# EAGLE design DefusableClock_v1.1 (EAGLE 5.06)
REV: 1.0
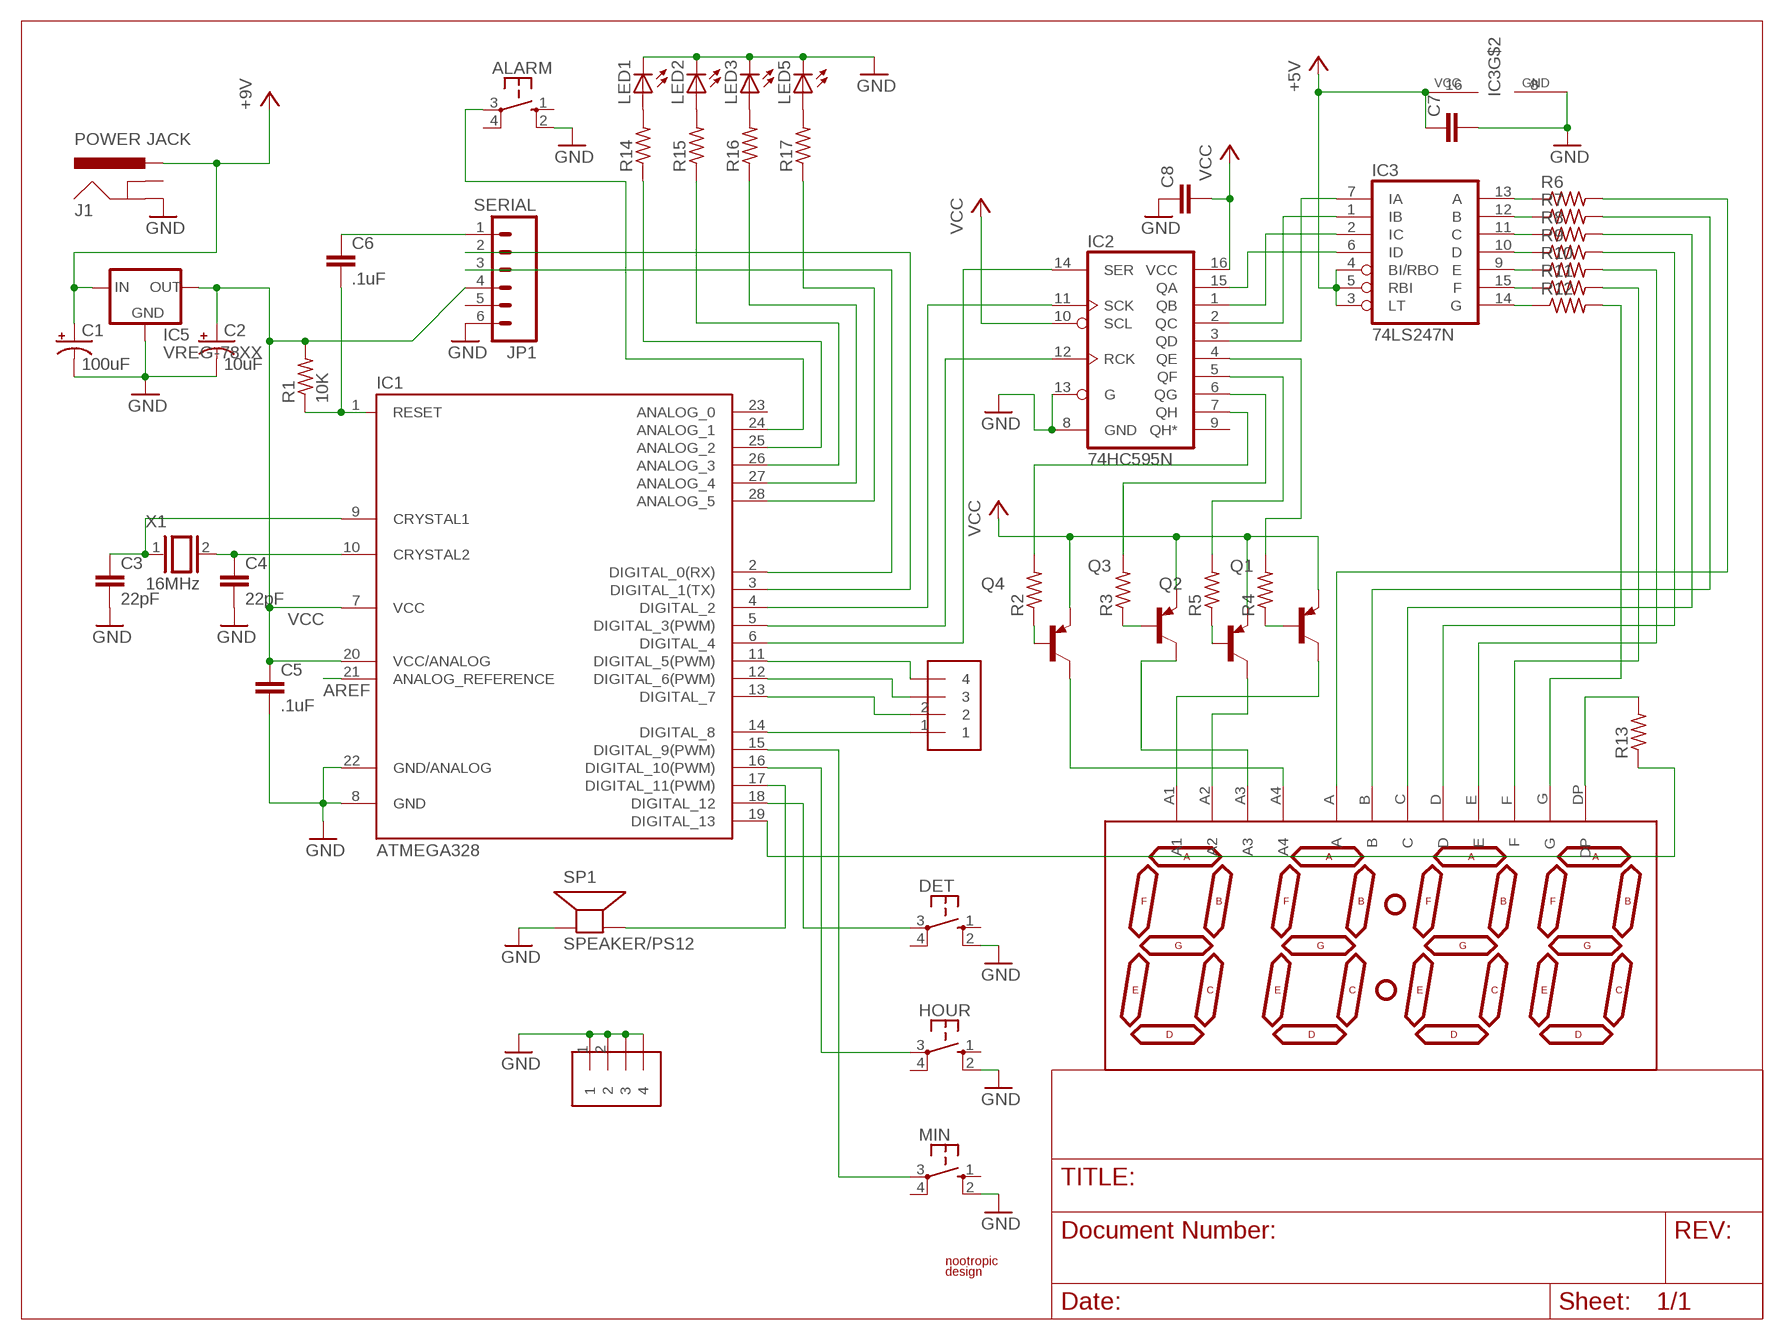
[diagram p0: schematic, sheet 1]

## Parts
ALARM  SWITCH-TACT  [SWITCH-TACT]
C1  100uF  CAP-POL6MM  [E2.5-6]
C2  10uF  CAP-POL5MM  [E2.5-5]
C3  22pF  CAP  [CAP-CERAMIC]
C4  22pF  CAP  [CAP-CERAMIC]
C5  .1uF  CAPSMALL  [CAP-CERAMIC-SMALL]
C6  .1uF  CAPSMALL  [CAP-CERAMIC-SMALL]
C7  CAPSMALL  [CAP-CERAMIC-SMALL]
C8  CAPSMALL  [CAP-CERAMIC-SMALL]
C9  1X4-TERMINAL-BLOCK  [1X4-TERMINAL]
C10  1X4-TERMINAL-BLOCK  [1X4-TERMINAL]
D1  7-SEGMENT-DISPLAY-4DIGIT  [7-SEGMENT-DISPLAY-4DIGIT]
DET  SWITCH-TACT12MM  [SWITCH-12MM]
HOUR  SWITCH-TACT  [SWITCH-TACT]
IC1  ATMEGA328  ATMEGA168-PU  [DIL28-3]
IC2  74HC595N  74LS595N  [DIL16]
IC3  74LS247N  74LS47N  [DIL16]
IC5  VREG-78XX  [78XXL]
J1  POWER JACK  POWER_JACKPTH  [POWER_JACK_PTH]
JP1  SERIAL  M06  [1X06]
LED1  LED3MM  [LED3MM]
LED2  LED3MM  [LED3MM]
LED3  LED3MM  [LED3MM]
LED5  LED3MM  [LED3MM]
MIN  SWITCH-TACT  [SWITCH-TACT]
Q1  -PNP-TO92-EBC  [TO92-EBC]
Q2  -PNP-TO92-EBC  [TO92-EBC]
Q3  -PNP-TO92-EBC  [TO92-EBC]
Q4  -PNP-TO92-EBC  [TO92-EBC]
R1  10K  R-US  [0207/10]
R2  R-US  [0207/10]
R3  R-US  [0207/10]
R4  R-US  [0207/10]
R5  R-US  [0207/10]
R6  R-US  [0207/10]
R7  R-US  [0207/10]
R8  R-US  [0207/10]
R9  R-US  [0207/10]
R10  R-US  [0207/10]
R11  R-US  [0207/10]
R12  R-US  [0207/10]
R13  R-US  [0207/10]
R14  R-US  [0207/10]
R15  R-US  [0207/10]
R16  R-US  [0207/10]
R17  R-US  [0207/10]
SP1  SPEAKER/PS12  [PS12]
U$1  LOGO  [LOGO_SMALL]
X1  16MHz  XTAL/S  [QS]

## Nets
A: D1.A R6.2
A1: D1.A1 Q1.C
A2: D1.A2 Q2.C
A3: D1.A3 Q3.C
A4: D1.A4 Q4.C
ALARM: ALARM.3(P) IC1.24(ANALOG_1)
AREF: IC1.21(ANALOG_REFERENCE)
ASINK: IC3.13(A) R6.1
B: D1.B R7.2
BSINK: IC3.12(B) R7.1
C: D1.C R8.2
CLOCK: IC1.4(DIGITAL_2) IC2.11(SCK)
CSINK: IC3.11(C) R8.1
D: D1.D R9.2
DATA: IC1.6(DIGITAL_4) IC2.14(SER)
DP: D1.DP R13.2
DSINK: IC3.10(D) R9.1
E: D1.E R10.2
ESINK: IC3.9(E) R10.1
F: D1.F R11.2
FSINK: IC3.15(F) R11.1
G: D1.G R12.2
GND: ALARM.2(S1) C1.- C2.- C3.2 C4.2 C5.2 C7.2 C8.1 C9.1 C9.2 C9.3 C9.4 DET.2(S1) HOUR.2(S1) IC1.8(GND) IC1.22(GND/ANALOG) IC2.8(GND) IC2.13(G) IC3.8(GND) IC5.GND J1.GND JP1.6 LED1.K(C) LED2.K(C) LED3.K(C) LED5.K(C) MIN.2(S1) SP1.P$1(+)
GSINK: IC3.14(G) R12.1
LATCH: IC1.5(DIGITAL_3(PWM)) IC2.12(RCK)
N$1: IC1.17(DIGITAL_11(PWM)) SP1.P$2(-)
N$2: IC2.3(QD) IC3.7(IA)
N$3: Q3.B R3.1
N$4: C4.1 IC1.10(CRYSTAL2) X1.2
N$5: Q2.B R5.1
N$6: C3.1 IC1.9(CRYSTAL1) X1.1
N$7: C6.2 IC1.1(RESET) R1.1
N$8: Q4.B R2.1
N$9: C6.1 JP1.1
N$10: IC2.2(QC) IC3.1(IB)
N$11: IC2.1(QB) IC3.2(IC)
N$12: IC2.15(QA) IC3.6(ID)
N$13: IC1.19(DIGITAL_13) R13.1
N$18: Q1.B R4.1
N$19: IC2.7(QH) R2.2
N$20: IC2.6(QG) R3.2
N$21: IC2.5(QF) R5.2
N$22: IC2.4(QE) R4.2
N$23: DET.3(P) IC1.18(DIGITAL_12)
N$24: HOUR.3(P) IC1.16(DIGITAL_10(PWM))
N$25: IC1.15(DIGITAL_9(PWM)) MIN.3(P)
N$26: LED1.A R14.2
N$27: LED2.A R15.2
N$28: LED3.A R16.2
N$29: IC1.28(ANALOG_5) R17.1
N$30: LED5.A R17.2
N$31: IC1.25(ANALOG_2) R14.1
N$32: IC1.26(ANALOG_3) R15.1
N$33: IC1.27(ANALOG_4) R16.1
RX: IC1.2(DIGITAL_0(RX)) JP1.3
TX: IC1.3(DIGITAL_1(TX)) JP1.2
VCC: C2.+ C5.1 C7.1 C8.2 IC1.7(VCC) IC1.20(VCC/ANALOG) IC2.10(SCL) IC2.16(VCC) IC3.3(LT) IC3.4(BI/RBO) IC3.5(RBI) IC3.16(VCC) IC5.OUT JP1.4 Q1.E Q2.E Q3.E Q4.E R1.2 ; supply symbol labelled +5V
VIN: C1.+ IC5.IN J1.PWR ; supply symbol labelled +9V
WIRE1: C10.4 IC1.11(DIGITAL_5(PWM))
WIRE2: C10.3 IC1.12(DIGITAL_6(PWM))
WIRE3: C10.2 IC1.13(DIGITAL_7)
WIRE4: C10.1 IC1.14(DIGITAL_8)
Unconnected: ALARM.1(S) ALARM.4(P1) DET.1(S) DET.4(P1) HOUR.1(S) HOUR.4(P1) IC1.23(ANALOG_0) IC2.9(QH*) J1.GNDBREAK JP1.5 MIN.1(S) MIN.4(P1)

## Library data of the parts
ALARM DET HOUR MIN = nootropicdesign:SWITCH-TACT: 12MM Tactile Switch
C1 C2 = nootropicdesign:CAP-POL: Capacitor - Polarized, Electrolytic
C3-C8 = nootropicdesign:CAP: Unpolarized capacitor
C9 C10 = nootropicdesign:1X4-TERMINAL-BLOCK
D1 = nootropicdesign:7-SEGMENT-DISPLAY-4DIGIT
IC1 = Arduino-AVR:ATMEGA168-PU
IC2 = nootropicdesign:74*595: 8-bit SHIFT REGISTER, output latch
IC3 = 74xx-us:74*47: BCD to seven segment DECODER/DRIVER Source: http://www.ee.washington.edu/stores/DataSheets/74ls/74ls47.pdf
IC5 = nootropicdesign:VREG-78XX
J1 = SparkFun:POWER_JACK: Power Jack This is the standard 5.5mm barrel jack for power. The PTH is the most common, proven, reliable, footprint. All others are experimental. The Slot footprint only works if the mill layer is transmitted to the PCB fab house so be warned. Spark Fun Electronics SKU : PRT-00119. Mating wall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
JP1 = nootropicdesign:M06: 6-pin header
LED1-LED3 LED5 = adafruit:LED: LED
Q1-Q4 = transistor-neu-to92:*-PNP-: PNP Transistror
R1-R17 = nootropicdesign:R-US: Resistor
SP1 = adafruit:SPEAKER: SPEAKER
U$1 = nootropicdesign:LOGO
X1 = special:XTAL/S: CRYSTAL

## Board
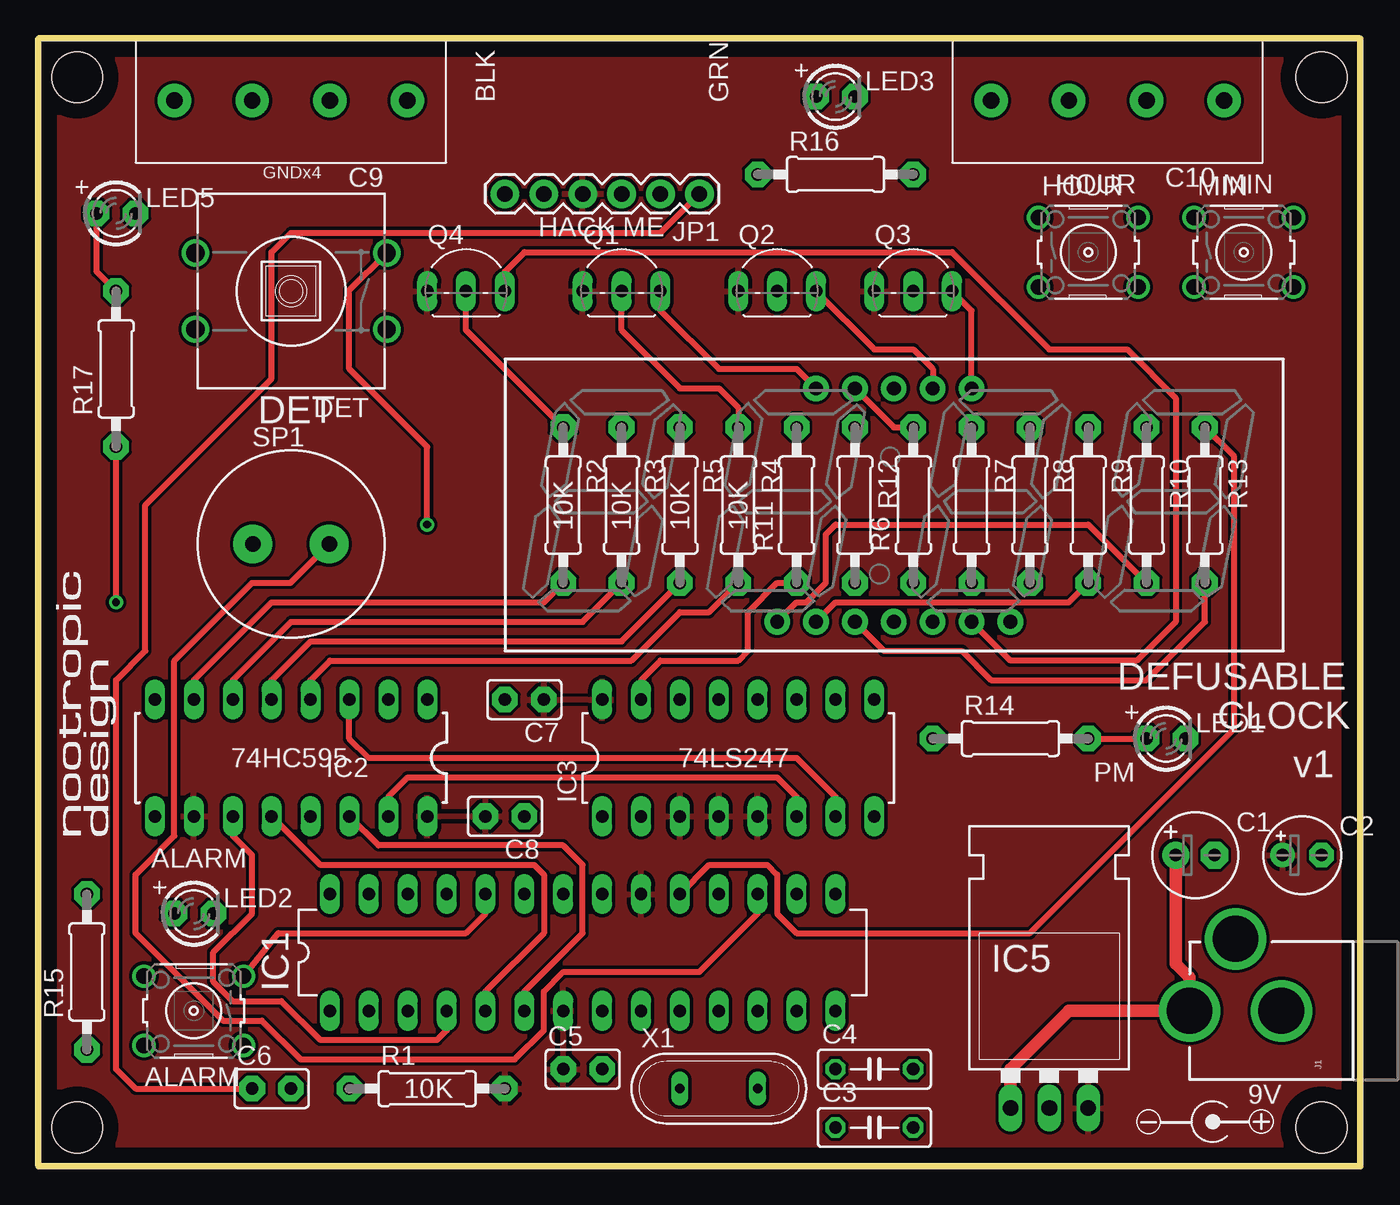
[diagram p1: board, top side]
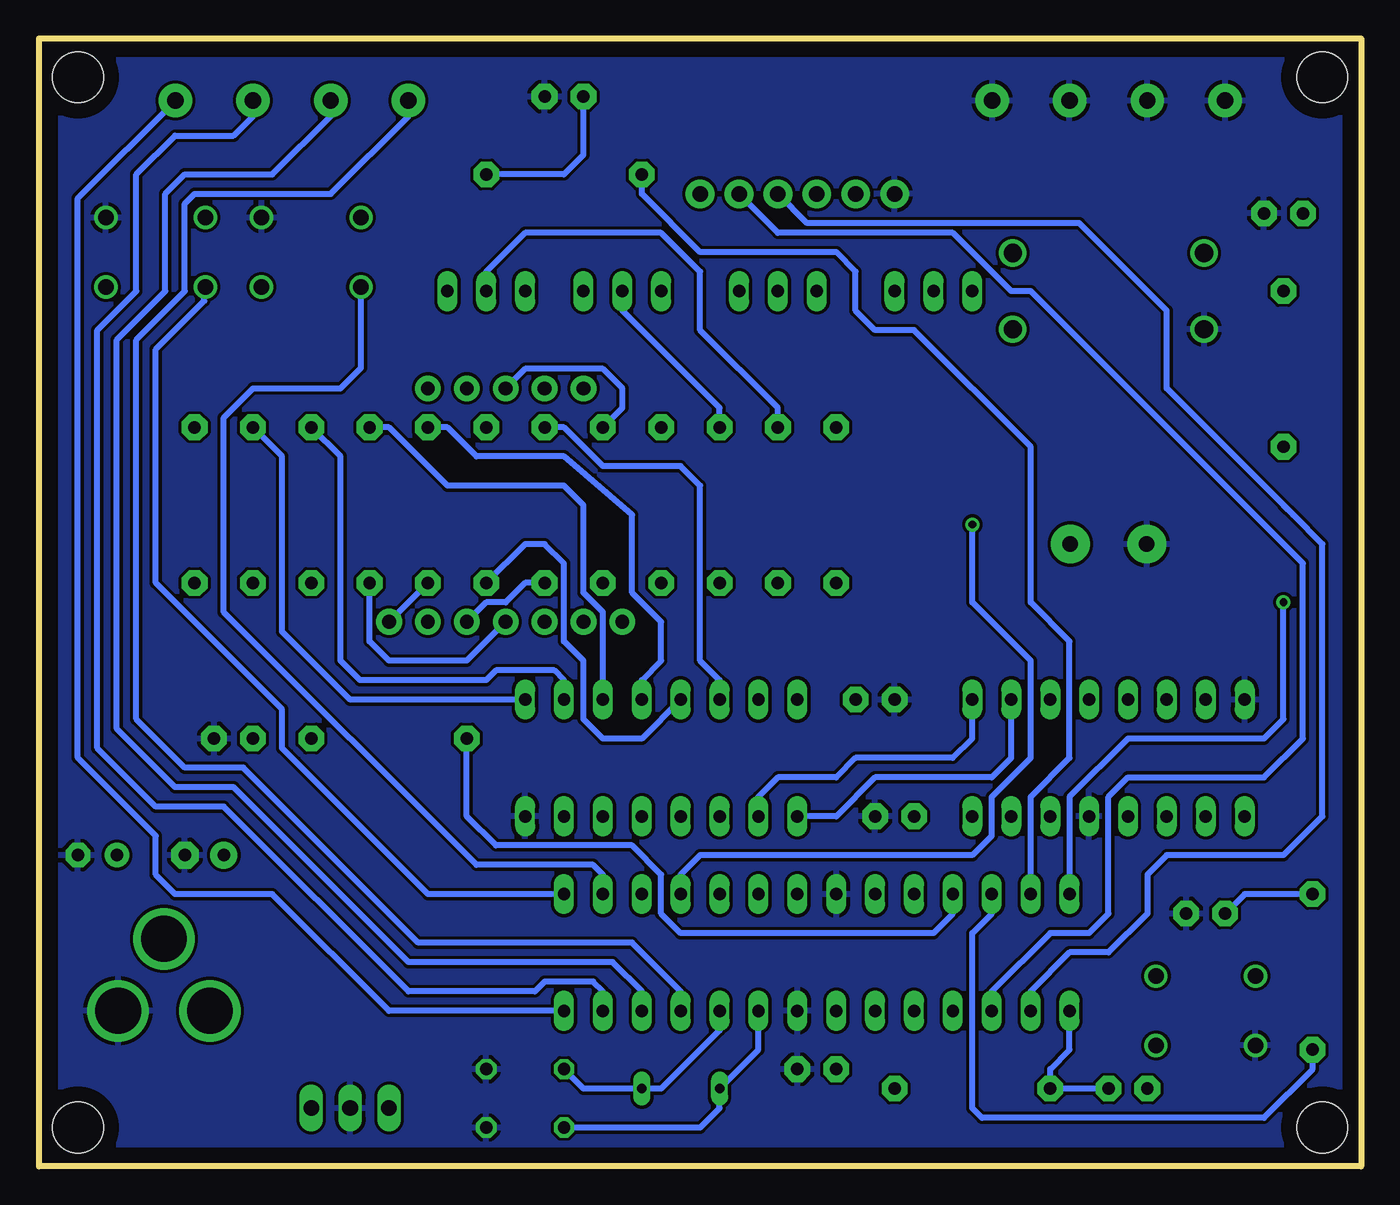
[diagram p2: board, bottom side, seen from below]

Size 86.41 x 73.66 mm. Coordinates in mm from the lower left corner, seen from the top.
Outline: 86.36,0 86.41,0 86.41,73.65 0,73.65 0,0
Outline: 0,0 86.36,0
Outline: 86.36,0 86.36,73.66 0,73.66 0,0
Copper layers (1*16): Top 0.035mm / dielectric 1.5mm / Bottom 0.035mm
Design rules "default *": minimum track width 10mil, minimum drill 20mil, track to track 8mil, track to pad 8mil, pad to pad 8mil, via to via 8mil, smd to smd 8mil, copper to edge 40mil, drill to drill 8mil, minimum pad ring 10mil, minimum via ring 8mil, stop-mask expansion 4mil, vias tented up to drill 0mil, thermal gap 10mil
Holes 3.3 mm at 2.54,71.12 83.82,71.12 83.82,2.54 2.54,2.54
tRestrict: area 33.8,7.2 to 34.1,8.8; area 35,9.3 to 35.2,11; area 34.5,7.3 to 34.8,8.8; area 34.1,30.7 to 35.9,30.9; area 34.1,30.1 to 35.9,30.3; area 36.6,31.9 to 37,32.1; area 37.6,30.3 to 37.7,30.7; area 36.6,28.9 to 37,29.1; area 25.2,24.3 to 25.6,24.4; area 25.2,21.3 to 25.6,21.4; area 24.5,22.7 to 24.7,23.1; area 26.3,23.1 to 28.1,23.3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

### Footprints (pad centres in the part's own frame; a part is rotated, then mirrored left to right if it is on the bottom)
SWITCH-TACT = drill 1.016 round: 1 -3.251,2.261; 2 3.251,2.261; 3 -3.251,-2.261; 4 3.251,-2.261
E2.5-6 = drill 0.813 pad 1.778 round: + -1.27,0 | drill 0.813 pad 1.778 octagon: - 1.27,0
E2.5-5 = drill 0.813 pad 1.6 round: + -1.27,0 | drill 0.813 pad 1.6 octagon: - 1.27,0
CAP-CERAMIC = drill 0.813 octagon: 1 -2.54,0; 2 2.54,0
CAP-CERAMIC-SMALL = drill 0.813 pad 1.676 octagon: 1 -1.27,0; 2 1.27,0
1X4-TERMINAL = drill 1.067 pad 2.184 round: 1 -3.785,-0.254; 2 1.27,-0.254; 3 6.35,-0.254; 4 11.43,-0.254
7-SEGMENT-DISPLAY-4DIGIT = drill 0.9 pad 1.676 round: A -2.54,7.62; A1 -5.08,7.62; A2 2.54,7.62; A3 5.08,7.62; A4 5.08,-7.62; B 7.62,-7.62; C 0,-7.62; D -5.08,-7.62; DP -2.54,-7.62; E -7.62,-7.62; F 0,7.62; G 2.54,-7.62
SWITCH-12MM = drill 1.194 round: 1 -6.248,2.489; 2 6.248,2.489; 3 -6.248,-2.489; 4 6.248,-2.489
DIL28-3 = drill 0.813 long: 1 -16.51,-3.81; 2 -13.97,-3.81; 3 -11.43,-3.81; 4 -8.89,-3.81; 5 -6.35,-3.81; 6 -3.81,-3.81; 7 -1.27,-3.81; 8 1.27,-3.81; 9 3.81,-3.81; 10 6.35,-3.81; 11 8.89,-3.81; 12 11.43,-3.81; 13 13.97,-3.81; 14 16.51,-3.81; 15 16.51,3.81; 16 13.97,3.81; 17 11.43,3.81; 18 8.89,3.81; 19 6.35,3.81; 20 3.81,3.81; 21 1.27,3.81; 22 -1.27,3.81; 23 -3.81,3.81; 24 -6.35,3.81; 25 -8.89,3.81; 26 -11.43,3.81; 27 -13.97,3.81; 28 -16.51,3.81
DIL16 = drill 0.813 long: 1 -8.89,-3.81; 2 -6.35,-3.81; 3 -3.81,-3.81; 4 -1.27,-3.81; 5 1.27,-3.81; 6 3.81,-3.81; 7 6.35,-3.81; 8 8.89,-3.81; 9 8.89,3.81; 10 6.35,3.81; 11 3.81,3.81; 12 1.27,3.81; 13 -1.27,3.81; 14 -3.81,3.81; 15 -6.35,3.81; 16 -8.89,3.81
78XXL = drill 1.016 long: GND 0,-5.08; IN -2.54,-5.08; OUT 2.54,-5.08
POWER_JACK_PTH = drill 2.997 round: GND 0,7.7; GNDBREAK 4.7,10.7; PWR 0,13.7
1X06 = drill 1.016 pad 1.88 round: 1 0,0; 2 2.54,0; 3 5.08,0; 4 7.62,0; 5 10.16,0; 6 12.7,0
LED3MM = drill 0.813 pad 1.676 octagon: A -1.27,0; K 1.27,0
TO92-EBC = drill 0.813 long: B 0,-1.27; C 2.54,-1.27; E -2.54,-1.27
0207/10 = drill 0.813 pad 1.676 octagon: 1 -5.08,0; 2 5.08,0
PS12 = drill 1 pad 2.54 round: P$1 -2.5,0; P$2 2.5,0
QS = drill 0.61 long: 1 -2.54,0; 2 2.54,0

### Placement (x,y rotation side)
ALARM  10.16,10.16 180 top
C1  75.56,20.32 0 top
C2  82.55,20.32 0 top
C3  54.61,2.54 0 top
C4  54.61,6.35 0 top
C5  35.56,6.35 0 top
C6  15.24,5.08 0 top
C7  31.75,30.48 180 top
C8  30.48,22.86 180 top
C9  20.32,69.34 180 top
C10  73.66,69.34 180 top
D1  55.88,43.18 0 top
DET  16.51,57.15 180 top
HOUR  68.58,59.69 0 top
IC1  35.56,13.97 0 top
IC2  16.51,26.67 180 top
IC3  45.72,26.67 0 top
IC5  66.04,8.89 0 top
J1  88.9,10.16 90 top
JP1  43.18,63.5 180 top
LED1  73.66,27.94 0 top
LED2  10.16,16.51 0 top
LED3  52.07,69.85 0 top
LED5  5.08,62.23 0 top
MIN  78.74,59.69 0 top
Q1  38.1,58.42 0 top
Q2  48.26,58.42 0 top
Q3  57.15,58.42 0 top
Q4  27.94,58.42 0 top
R1  25.4,5.08 0 top
R2  34.29,43.18 270 top
R3  38.1,43.18 270 top
R4  45.72,43.18 270 top
R5  41.91,43.18 270 top
R6  57.15,43.18 90 top
R7  60.96,43.18 270 top
R8  64.77,43.18 270 top
R9  68.58,43.18 270 top
R10  72.39,43.18 270 top
R11  49.53,43.18 90 top
R12  53.34,43.18 270 top
R13  76.2,43.18 270 top
R14  63.5,27.94 0 top
R15  3.17,12.7 90 top
R16  52.07,64.77 0 top
R17  5.08,52.07 90 top
SP1  16.51,40.64 0 top
U$1  5.08,21.59 90 top
X1  44.45,5.08 0 top

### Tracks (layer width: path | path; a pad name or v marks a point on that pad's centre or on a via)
A
  Top 0.406: D1.A 55.88,48.26 R6.2
A1
  Top 0.406: Q1.C 40.64,55.88 44.45,52.07 49.53,52.07 D1.A1
A2
  Top 0.406: Q2.C 54.61,53.34 57.15,53.34 58.42,52.07 D1.A2
A3
  Top 0.406: Q3.C 60.96,55.88 D1.A3
A4
  Top 0.406: Q4.C 30.48,58.42 31.75,59.69 59.69,59.69 66.04,53.34 71.12,53.34 74.3,50.16 74.3,35.56 71.75,33.02 63.5,33.02 D1.A4
ALARM
  Top 0.406: IC1.24 29.21,16.51 27.94,15.24 15.67,15.24 ALARM.3
ASINK
  Bottom 0.406: IC3.13 46.99,27.94 49.53,27.94 50.8,29.21 50.8,33.02 52.07,34.29 52.07,39.37 53.34,40.64 54.61,40.64 R6.1
B
  Bottom 0.406: D1.B R7.2
BSINK
  Bottom 0.406: R7.1 59.69,48.26 57.78,46.35 52.07,46.35 47.62,42.55 47.62,37.47 45.72,35.56 45.72,33.02 46.99,31.75 IC3.12
C
  Bottom 0.406: R8.2 64.77,34.29 63.5,33.02 58.42,33.02 D1.C
CLOCK
  Top 0.406: IC1.4 26.67,8.89 26.04,8.26 18.41,8.26 15.88,10.79 12.7,10.79 11.43,12.06 11.43,13.97 13.97,16.51 13.97,20.32 12.7,21.59 IC2.11
CSINK
  Bottom 0.406: IC3.11 49.53,36.2 50.8,37.47 50.8,43.18 52.07,44.45 59.69,44.45 63.5,48.26 R8.1
D
  Top 0.406: D1.D 52.07,36.83 67.31,36.83 R9.2
DATA
  Top 0.406: IC1.6 31.75,11.43 35.56,15.24 35.56,19.68 34.29,20.95 22.23,20.95 IC2.14
DP
  Top 0.406: R13.2 76.2,35.56 72.39,31.75 62.23,31.75 60.33,33.66 55.24,33.66 D1.DP
DSINK
  Bottom 0.406: IC3.10 52.07,31.75 52.7,32.38 56.52,32.38 57.15,31.75 65.41,31.75 66.67,33.02 66.67,46.35 R9.1
E
  Top 0.406: D1.E 49.53,36.83 50.16,36.83 51.44,38.1 51.44,41.27 52.07,41.91 68.58,41.91 R10.2
ESINK
  Bottom 0.406: IC3.9 66.04,30.48 70.48,34.92 70.48,46.35 R10.1
F
  Bottom 0.406: R11.2 48.26,49.53 48.26,50.8 49.53,52.07 54.61,52.07 D1.F
FSINK
  Top 0.406: R11.1 48.26,38.1 46.35,36.2 46.35,33.66 45.72,33.02 40.64,33.02 39.37,31.75 IC3.15
G
  Bottom 0.406: R12.2 54.61,38.1 55.88,36.83 57.15,36.83 D1.G
GND
  pour Bottom: 0.51,0.51 85.85,0.51 85.85,73.15 0.51,73.15
GSINK
  Bottom 0.406: IC3.14 41.91,31.75 43.18,33.02 43.18,44.45 44.45,45.72 49.53,45.72 52.07,48.26 R12.1
LATCH
  Top 0.406: IC1.5 29.21,11.43 33.02,15.24 33.02,19.05 32.38,19.68 18.41,19.68 IC2.12
N$1
  Top 0.406: IC1.17 46.99,16.51 43.18,12.7 34.29,12.7 33.02,11.43 33.02,8.89 31.11,6.99 17.14,6.99 14.61,9.53 12.06,9.53 6.35,15.24 6.35,19.05 8.89,21.59 8.89,33.02 13.97,38.1 16.47,38.1 SP1.P$2
N$2
  Top 0.406: IC2.3 20.32,27.94 21.59,26.67 49.53,26.67 52.07,24.13 IC3.7
N$3
  Bottom 0.406: R3.1 38.1,49.53 43.18,54.61 43.18,58.42 45.72,60.96 54.61,60.96 57.15,58.42 Q3.B
N$4
  Bottom 0.406: IC1.10 41.91,8.89 45.72,5.08 X1.2 50.8,5.08 C4.1
N$5
  Bottom 0.406: R5.1 41.91,49.53 48.26,55.88 Q2.B
N$6
  Bottom 0.406: IC1.9 39.37,7.62 X1.1 41.91,3.81 43.18,2.54 C3.1
N$7
  Bottom 0.406: C6.2 R1.1 20.32,6.35 19.05,7.62 IC1.1
N$8
  Top 0.406: R2.1 27.94,54.61 Q4.B
N$9
  Top 0.406: JP1.1 40.64,60.96 16.51,60.96 15.24,59.69 15.24,51.44 6.99,43.18 6.99,33.66 5.08,31.75 5.08,6.35 6.35,5.08 C6.1
N$10
  Bottom 0.406: IC2.2 22.86,26.67 24.13,25.4 31.75,25.4 34.29,22.86 IC3.1
N$11
  Bottom 0.406: IC3.2 39.37,24.13 38.1,25.4 34.29,25.4 33.02,26.67 26.67,26.67 25.4,27.94 IC2.1
N$12
  Top 0.406: IC3.6 49.53,24.13 48.26,25.4 24.13,25.4 22.86,24.13 IC2.15
N$13
  Top 0.406: IC1.19 43.81,19.68 47.62,19.68 48.26,19.05 48.26,16.51 49.53,15.24 64.77,15.24 78.11,28.57 78.11,46.35 R13.1
N$18
  Top 0.406: R4.1 45.72,49.53 44.45,50.8 41.91,50.8 38.1,54.61 Q1.B
N$19
  Top 0.406: IC2.7 10.16,31.75 15.24,36.83 33.02,36.83 R2.2
N$20
  Top 0.406: IC2.6 12.7,31.75 16.51,35.56 35.56,35.56 R3.2
N$21
  Top 0.406: IC2.5 15.24,31.75 17.78,34.29 38.1,34.29 R5.2
N$22
  Top 0.406: IC2.4 17.78,31.75 19.05,33.02 38.73,33.02 41.91,36.2 43.81,36.2 R4.2
N$23  (via drill 0.51)
  Top 0.406: v25.4,41.91 25.4,46.99 20.32,52.07 20.32,57.2 DET.3
  Bottom 0.406: IC1.18 44.45,19.05 43.18,20.32 25.4,20.32 24.13,21.59 24.13,24.13 21.59,26.67 21.59,33.02 25.4,36.83 v25.4,41.91
N$24
  Bottom 0.406: IC1.16 49.53,19.05 50.16,19.68 57.78,19.68 74.3,36.2 74.3,48.9 72.39,50.8 66.67,50.8 65.33,52.15 HOUR.3
N$25
  Bottom 0.406: MIN.3 75.56,57.35 75.56,56.52 78.74,53.34 78.74,38.1 70.48,29.84 70.48,27.3 60.96,17.78 IC1.15
N$26
  Top 0.406: R14.2 LED1.A
N$27
  Bottom 0.406: R15.2 7.62,17.78 LED2.A
N$28
  Bottom 0.406: R16.2 52.07,64.77 50.8,66.04 LED3.A
N$29  (via drill 0.51)
  Top 0.406: v5.08,36.83 R17.1
  Bottom 0.406: IC1.28 19.05,24.13 15.24,27.94 6.35,27.94 5.08,29.21 v5.08,36.83
N$30
  Top 0.406: R17.2 3.81,58.42 LED5.A
N$31
  Bottom 0.406: IC1.25 26.67,16.51 27.94,15.24 44.45,15.24 45.72,16.51 45.72,19.05 47.62,20.95 56.52,20.95 58.42,22.86 R14.1
N$32
  Bottom 0.406: R15.1 3.17,6.35 6.35,3.17 24.77,3.17 25.4,3.81 25.4,15.24 24.13,16.51 IC1.26
N$33
  Bottom 0.406: R16.1 46.99,63.5 43.18,59.69 34.29,59.69 33.02,58.42 33.02,55.88 31.75,54.61 29.21,54.61 21.59,46.99 21.59,36.83 19.05,34.29 19.05,26.67 21.59,24.13 IC1.27
RX
  Bottom 0.406: JP1.3 36.2,61.59 18.41,61.59 12.7,55.88 12.7,50.8 4.45,42.55 | 4.45,42.55 2.54,40.64 2.54,22.86 5.08,20.32 12.7,20.32 13.97,19.05 13.97,16.51 16.51,13.97 19.05,13.97 21.59,11.43 IC1.2 | 4.45,42.55 5.08,43.18
TX
  Bottom 0.406: JP1.2 38.1,60.96 26.67,60.96 22.86,57.15 21.59,57.15 3.81,39.37 3.81,27.94 6.35,25.4 15.24,25.4 16.51,24.13 16.51,16.51 17.78,15.24 20.32,15.24 24.13,11.43 IC1.3
VCC
  pour Top: 0.51,0.51 85.85,0.51 85.85,73.15 0.51,73.15
VIN
  Top 0.813: IC5.IN 63.5,6.35 67.31,10.16 J1.PWR 75.2,12.34 74.3,13.25 C1.+
WIRE1
  Bottom 0.406: IC1.11 44.45,11.43 47.62,14.61 61.59,14.61 73.03,26.04 76.83,26.04 80.01,29.21 80.01,53.98 76.83,57.15 76.83,62.87 76.2,63.5 67.31,63.5 62.23,68.58 C10.4
WIRE2
  Bottom 0.406: IC1.12 46.99,11.43 48.9,13.34 62.23,13.34 73.66,24.77 77.47,24.77 81.28,28.57 81.28,53.98 78.11,57.15 78.11,63.5 76.83,64.77 71.12,64.77 67.31,68.58 C10.3
WIRE3
  Bottom 0.406: IC1.13 49.53,11.43 50.16,12.06 53.34,12.06 53.98,11.43 62.23,11.43 74.3,23.5 78.74,23.5 82.55,27.3 82.55,54.61 80.01,57.15 80.01,64.77 77.47,67.31 73.66,67.31 72.39,68.58 C10.2
WIRE4
  Bottom 0.406: IC1.14 63.5,10.16 71.12,17.78 77.47,17.78 78.74,19.05 78.74,21.59 83.82,26.67 83.82,63.22 C10.1

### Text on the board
tPlace: BLK | GRN | GNDx4 | HOUR | MIN | HACK ME | DET | 10K | 10K | 10K | 10K | 10K | DEFUSABLE | CLOCK | 74HC595 | 74LS247 | PM | v1 | ALARM | 10K | 9V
